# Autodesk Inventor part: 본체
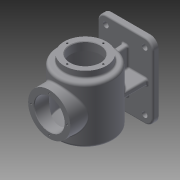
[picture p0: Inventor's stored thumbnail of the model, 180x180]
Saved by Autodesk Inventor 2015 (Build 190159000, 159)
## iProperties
Created: 2016-09
Part Number: 본체
Material: 일반
Document SubType Name: Modeling
Designer: LineLG02
Density: 1 g/cm^3
Appearance: 기본값
Author: LineLG02
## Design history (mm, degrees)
sketch "스케치1"
  geometry: L1 (0, 0)-(0, 122); L2 (0, 122)-(38, 122); L3 (38, 122)-(38, 110); L4 (38, 110)-(45, 110); L5 (0, 0)-(38, 0); L6 (50, 14.626)-(50, 22); L7 (50, 14.626)-(50, 105); A1 r 115 centre (0, 115) between (0, 0) and (47.045, 10.063); A2 r 5 centre (45, 105) between (50, 105) and (45, 110); A3 r 5 centre (45, 14.626) between (47.045, 10.063) and (50, 14.626); 1 further point
  constraints: 14 end point, 7 point on circle, 5 tangent, 3 centre point, 3 point on line, 2 horizontal, 2 parallel, 2 perpendicular, 1 equal radius, 1 vertical
  dimensions: "d0" = 122 distance of L1.start L1.end; "d11" = 5 radius of A2
revolve "회전1" sketch "스케치1" stored, may be unused: angle "d12" = 90 deg
sketch "스케치2"
  geometry: L1 (0, 0)-(0, 122); L2 (-27, 107)-(-27, 122); L3 (-27, 107)-(-45, 107); L4 (-47, 105)-(-47, 14.626); L5 (-50, 105)-(-50, 14.626) reference; L6 (0, 122)-(-27, 122); A1 r 115 centre (0, 115) between (-47.045, 10.063) and (47.045, 10.063) reference; A2 r 5 centre (-45, 14.626) between (-50, 14.626) and (-47.045, 10.063) reference; A3 r 112 centre (0, 115) between (-45.818, 12.801) and (0, 3); A4 r 2 centre (-45, 105) between (-45, 107) and (-47, 105); A5 r 2 centre (-45, 14.626) between (-47, 14.626) and (-45.818, 12.801); 1 further point
  constraints: 10 end point, 7 point on circle, 4 tangent, 3 centre point, 2 horizontal, 2 point on line, 1 equal radius, 1 parallel, 1 perpendicular, 1 vertical
  dimensions: "d17" = 3 radial gap between concentric circles of A1 A3; "d19" = 2 radius of A4
revolve "회전2" sketch "스케치2" stored, may be unused: angle "d20" = 90 deg
node "작업 평면1"
sketch "스케치3"
  geometry: L1 (-38, 122)-(38, 122) reference; L2 (-38, 60)-(38, 60); C1 r 38 at (0, 60); 1 further point
  constraints: 2 end point, 1 centre point, 1 midpoint, 1 parallel
  dimensions: "d22" = 62 distance between parallel lines of L1 L2; "d23" = 76 diameter of C1
extrude "돌출1" join sketch "스케치3" stored distance "d24" = 10; taper "d25" = 0 deg
sketch "스케치4"
  geometry: C1 r 38 at (0, 0) reference; C2 r 27 at (0, 0); 1 further point
  constraints: 1 centre point, 1 coincident
  dimensions: "d26" = 54 diameter of C2
extrude "돌출2" cut sketch "스케치4" stored distance "d27" = 10; taper "d28" = 0 deg
node "작업 평면2"
sketch "스케치5"
  geometry: L1 (-38, 62)-(38, 62) reference; L2 (-50, 68.5)-(50, 68.5); L3 (50, 68.5)-(50, -66.5); L4 (50, -66.5)-(-50, -66.5); L5 (-50, -66.5)-(-50, 68.5); L6 (-50, 68.5)-(50, -66.5); L7 (50, 68.5)-(-50, -66.5); 2 further points
  constraints: 12 end point, 2 midpoint, 2 parallel, 1 horizontal, 1 perpendicular
  dimensions: "d30" = 100 distance of L3.end L4.end; "d31" = 135 distance of L2.end L3.end
extrude "돌출3" join sketch "스케치5" distance "d32" = 10; taper "d33" = 0 deg
node "작업 평면3"
sketch "스케치6"
  geometry: L1 (107.5, -10)-(105.482, -33.062); L2 (107.5, -10)-(27.5, -10); L3 (27.5, -10)-(29.518, -33.062); L4 (105.482, -33.062)-(29.518, -33.062); 3 further points
  constraints: 8 end point, 2 horizontal
  dimensions: "d44" = 95 deg angle of L2 L1; "d45" = 95 deg angle of L2 L3
extrude "돌출4" join sketch "스케치6" stored distance "d46" = 10; taper "d47" = 0 deg
node "작업 평면4"
sketch "스케치7"
  geometry: L1 (100, 0)-(100, -10) reference; L2 (50, 0)-(50, -10); L3 (90, 0)-(90, -54.513); L4 (10, 0)-(10, -10); L5 (10, -10)-(10, -54.513); L6 (10, -10)-(90, -10); L7 (100, -10)-(0, -10) reference; A1 r 48.534 centre (50, -82) between (90, -54.513) and (10, -54.513); 1 further point
  constraints: 10 end point, 3 parallel, 2 point on circle, 2 point on line, 1 centre point, 1 coincident, 1 vertical
  dimensions: "d48" = 50 distance between parallel lines of L1 L2; "d49" = 40 distance between parallel lines of L2 L3; "d50" = 40 distance between parallel lines of L2 L4
extrude "돌출5" join sketch "스케치7" stored distance "d51" = 10; taper "d52" = 0 deg
sketch "스케치8"
  geometry: L1 (50, 68.5)-(50, -66.5) reference; L2 (-50, 68.5)-(50, 68.5) reference; L3 (50, 68.5)-(50, -66.5) reference; L4 (50, -66.5)-(-50, -66.5) reference; L5 (-50, -66.5)-(-50, 68.5) reference; L6 (50, 68.5)-(35, 68.5); L7 (-35, 68.5)-(-50, 68.5); L8 (50, -66.5)-(50, -51.5); L9 (50, 53.5)-(50, 68.5); L10 (-50, -66.5)-(-35, -66.5); L11 (35, -66.5)-(50, -66.5); L12 (-50, 68.5)-(-50, 53.5); L13 (-50, -51.5)-(-50, -66.5); A1 r 15 centre (35, 53.5) between (50, 53.5) and (35, 68.5); A2 r 15 centre (-35, 53.5) between (-35, 68.5) and (-50, 53.5); A3 r 15 centre (35, -51.5) between (35, -66.5) and (50, -51.5); A4 r 15 centre (-35, -51.5) between (-50, -51.5) and (-35, -66.5); 1 further point
  constraints: 16 end point, 8 parallel, 8 point on circle, 8 tangent, 4 centre point, 4 perpendicular, 2 horizontal
  dimensions: "d53" = 15 radius of A1; "d54" = 15 radius of A2; "d55" = 15 radius of A3; "d56" = 15 radius of A4
extrude "돌출6" cut sketch "스케치8" stored distance "d57" = 10; taper "d58" = 0 deg
sketch "스케치9"
  geometry: A1 r 15 centre (35, 53.5) between (50, 53.5) and (35, 68.5) reference; A2 r 15 centre (-35, 53.5) between (-35, 68.5) and (-50, 53.5) reference; A3 r 15 centre (-35, -51.5) between (-50, -51.5) and (-35, -66.5) reference; A4 r 15 centre (35, -51.5) between (35, -66.5) and (50, -51.5) reference; 1 further point
hole "구멍1" sketch "스케치9" at (35, 53.5), (-35, 53.5), (-35, -51.5), (35, -51.5) diameter "d59" = 10; stored, may be unused: countersink angle "d63" = 90 deg, drill point angle "d65" = 0 deg; dims "d60" = 6, "d61" = 4, "d62" = 2, "d64" = 8
sketch "스케치10" dims "d66" = 65
  geometry: L1 (0, 0)-(0, -41.057); 2 further points
  constraints: 2 end point, 1 coincident, 1 point on line, 1 vertical, 1 vertical alignment, 2 other
hole "구멍2" sketch "스케치10" at (0, -32.5) diameter "d67" = 3.242; stored, may be unused: countersink angle "d71" = 90 deg, drill point angle "d73" = 118 deg; dims "d68" = 8, "d69" = 4, "d70" = 2, "d72" = 10
sketch "스케치11" dims "d77" = 65
  geometry: L1 (0, 0)-(0, 34.462); C1 r 38 at (0, 0) reference; 2 further points
  constraints: 2 end point, 1 coincident, 1 point on line, 1 vertical, 1 vertical alignment, 2 other
hole "구멍3" sketch "스케치11" at (0, 32.5) diameter "d78" = 3.242; stored, may be unused: countersink angle "d82" = 90 deg, drill point angle "d84" = 118 deg; dims "d79" = 8, "d80" = 4, "d81" = 2, "d83" = 10
chamfer "모따기1" distance "d88" = 1; stored, may be unused: second distance "d89" = 2, angle "d90" = 45 deg
chamfer "모따기2" distance "d91" = 1; stored, may be unused: second distance "d92" = 2, angle "d93" = 45 deg
fillet "모깎기1" dims "d94" = 3
node "작업 평면10"
  node "작업 평면9"
sketch "스케치15"
  geometry: 2 further points
  constraints: 1 coincident, 1 other
extrude "돌출7" join sketch "스케치15" stored distance "d98" = 10; taper "d99" = 0 deg
fillet "모깎기2" dims "d100" = 3
node "솔리드1"
pattern_circular "원형 패턴1" dims angle "d75" = 360 deg
pattern_circular "원형 패턴2" dims angle "d86" = 360 deg
node "투영된 루프1"
node "투영된 루프2"
other parameters: "d21" = -65, "d29" = -147, "d97" = 0.5
